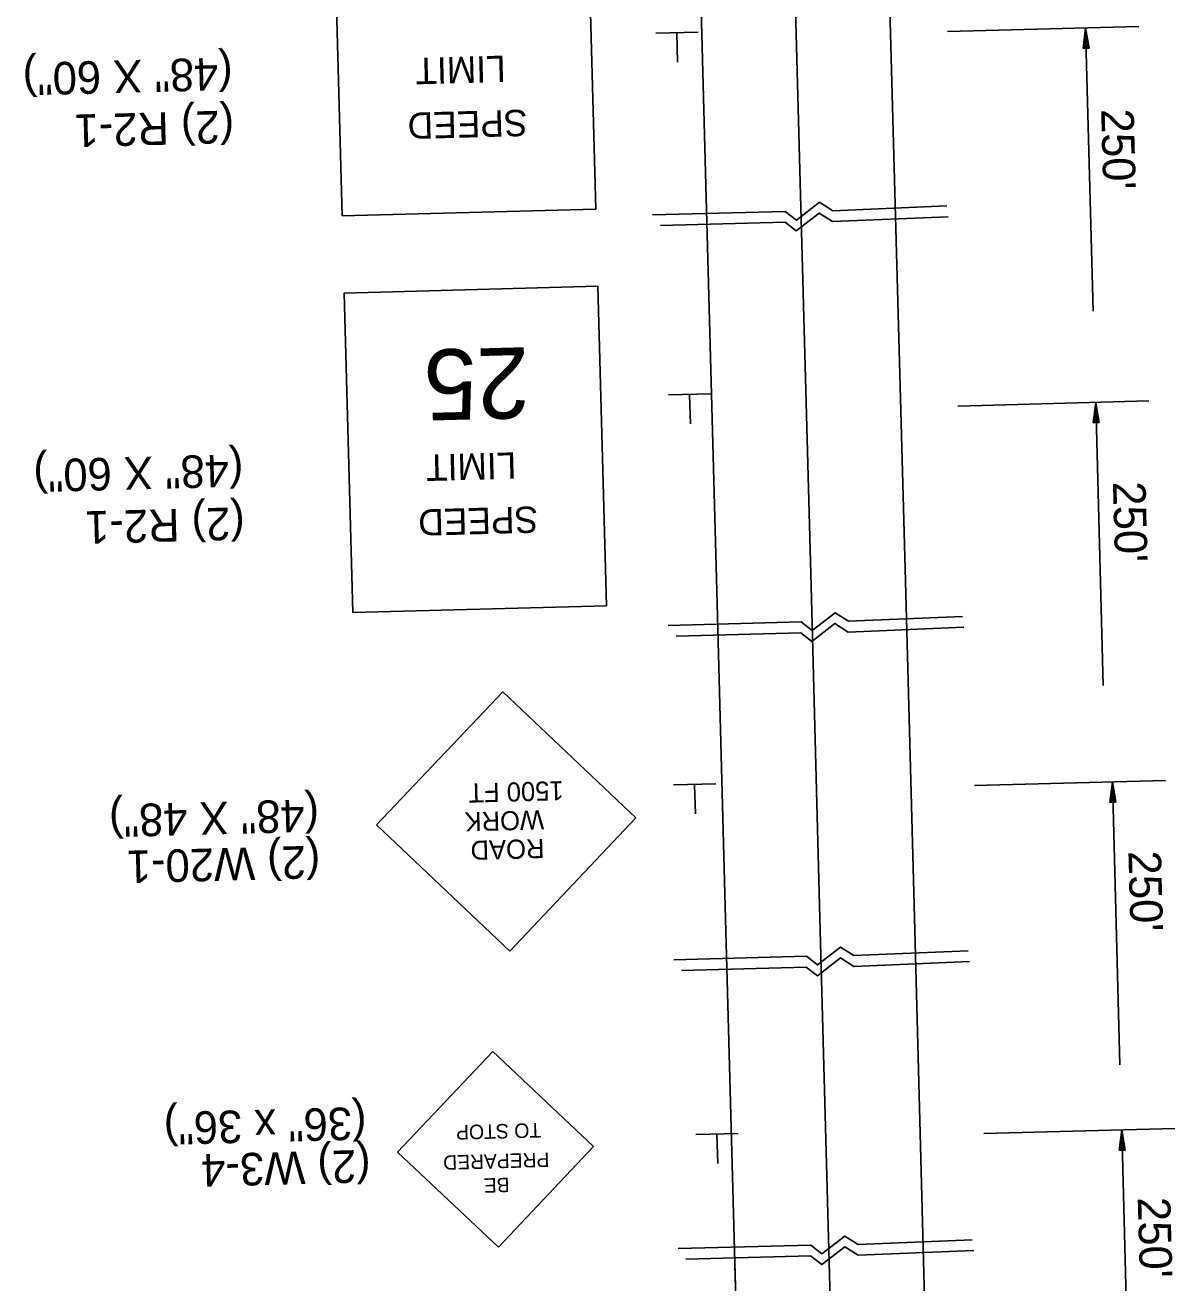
# Model space of a CAD drawing. Extents: x 1929624 to 1932072, y 596315 to 605533.
# Drawn here: x 1931202.8 to 1931414.6, y 596981 to 597212.7 of the extents above; entities that cross this region are included whole.
import ezdxf

# ---------------------------------------------------------------- set-up
doc = ezdxf.new("R2010")
doc.units = 0
doc.layers.add('Default', color=7, linetype='Continuous')

msp = doc.modelspace()

# ---------------------------------------------------------------- linework, layer by layer
at = {"layer": 'Default'}
for p, q in [((1931326.37, 597252.24), (1931328.22, 597183.26)), ((1931343.74, 597252.71), (1931345.6, 597183.73)), ((1931361.12, 597253.18), (1931362.97, 597184.2)), ((1931318.98, 597211.23), (1931326.8, 597211.44)), ((1931322.87, 597211.22), (1931323.01, 597205.88)), ((1931407.94, 597212.46), (1931372.74, 597211.52)), ((1931397.69, 597208.44), (1931398.15, 597212.2)), ((1931397.79, 597208.44), (1931398.17, 597211.57)), ((1931397.88, 597208.44), (1931398.19, 597210.93)), ((1931397.98, 597208.44), (1931398.21, 597210.31)), ((1931398.15, 597212.2), (1931399.55, 597160.03)), ((1931398.82, 597208.47), (1931398.15, 597212.2)), ((1931398.72, 597208.46), (1931398.17, 597211.57)), ((1931398.63, 597208.46), (1931398.19, 597210.93)), ((1931398.53, 597208.46), (1931398.21, 597210.31)), ((1931397.69, 597208.44), (1931398.82, 597208.47)), ((1931398.07, 597208.45), (1931398.22, 597209.67)), ((1931398.17, 597208.45), (1931398.24, 597209.04)), ((1931398.44, 597208.46), (1931398.22, 597209.67)), ((1931398.34, 597208.45), (1931398.24, 597209.04)), ((1931328.22, 597183.26), (1931330.23, 597108.43)), ((1931345.6, 597183.73), (1931347.59, 597109.36)), ((1931362.97, 597184.2), (1931364.96, 597110.29)), ((1931321.33, 597144.6), (1931329.15, 597144.81)), ((1931325.22, 597144.59), (1931325.37, 597139.25)), ((1931409.79, 597143.48), (1931374.6, 597142.54)), ((1931399.54, 597139.46), (1931400.01, 597143.22)), ((1931400.01, 597143.22), (1931401.41, 597091.05)), ((1931400.67, 597139.49), (1931400.01, 597143.22)), ((1931399.64, 597139.46), (1931400.02, 597142.6)), ((1931399.73, 597139.46), (1931400.04, 597141.95)), ((1931399.83, 597139.46), (1931400.06, 597141.33)), ((1931400.58, 597139.48), (1931400.02, 597142.6)), ((1931400.48, 597139.48), (1931400.04, 597141.95)), ((1931400.39, 597139.48), (1931400.06, 597141.33)), ((1931399.54, 597139.46), (1931400.67, 597139.49)), ((1931399.92, 597139.47), (1931400.07, 597140.69)), ((1931400.02, 597139.47), (1931400.09, 597140.06)), ((1931400.29, 597139.48), (1931400.07, 597140.69)), ((1931400.19, 597139.47), (1931400.09, 597140.06)), ((1931330.23, 597108.43), (1931331.85, 597048.08)), ((1931347.59, 597109.36), (1931349.23, 597048.2)), ((1931364.96, 597110.29), (1931366.62, 597048.33)), ((1931267.55, 597065.36), (1931290.8, 597089.88)), ((1931290.8, 597089.88), (1931315.34, 597066.65)), ((1931412.87, 597073.58), (1931377.67, 597072.63)), ((1931322.25, 597072.73), (1931330.07, 597072.94)), ((1931326.14, 597072.72), (1931326.29, 597067.38)), ((1931402.62, 597069.55), (1931403.08, 597073.31)), ((1931402.71, 597069.55), (1931403.1, 597072.69)), ((1931402.81, 597069.55), (1931403.12, 597072.04)), ((1931402.9, 597069.56), (1931403.13, 597071.42)), ((1931403.08, 597073.31), (1931404.48, 597021.14)), ((1931403.75, 597069.58), (1931403.08, 597073.31)), ((1931403.65, 597069.58), (1931403.1, 597072.69)), ((1931403.56, 597069.57), (1931403.12, 597072.04)), ((1931403.46, 597069.57), (1931403.13, 597071.42)), ((1931402.62, 597069.55), (1931403.75, 597069.58)), ((1931403, 597069.56), (1931403.15, 597070.78)), ((1931403.09, 597069.56), (1931403.17, 597070.16)), ((1931403.37, 597069.57), (1931403.15, 597070.78)), ((1931403.27, 597069.57), (1931403.17, 597070.16)), ((1931292.08, 597042.11), (1931315.34, 597066.65)), ((1931267.55, 597065.36), (1931292.08, 597042.11)), ((1931331.85, 597048.08), (1931333.84, 596973.76)), ((1931349.23, 597048.2), (1931350.88, 596987.04)), ((1931366.62, 597048.33), (1931368.25, 596987.51)), ((1931271.44, 597005.06), (1931288.96, 597023.61)), ((1931288.96, 597023.61), (1931307.51, 597006.09)), ((1931414.59, 597009.44), (1931379.39, 597008.49)), ((1931404.34, 597005.41), (1931404.8, 597009.18)), ((1931404.8, 597009.18), (1931406.2, 596957.01)), ((1931405.47, 597005.44), (1931404.8, 597009.18)), ((1931326.36, 597008.33), (1931334.18, 597008.54)), ((1931330.26, 597008.32), (1931330.4, 597002.98)), ((1931404.44, 597005.41), (1931404.82, 597008.55)), ((1931404.53, 597005.42), (1931404.84, 597007.9)), ((1931404.63, 597005.42), (1931404.85, 597007.28)), ((1931404.72, 597005.42), (1931404.87, 597006.64)), ((1931405.37, 597005.44), (1931404.82, 597008.55)), ((1931405.28, 597005.44), (1931404.84, 597007.9)), ((1931405.18, 597005.43), (1931404.85, 597007.28)), ((1931405.09, 597005.43), (1931404.87, 597006.64)), ((1931271.44, 597005.06), (1931289.99, 596987.55)), ((1931289.99, 596987.55), (1931307.51, 597006.09)), ((1931404.34, 597005.41), (1931405.47, 597005.44)), ((1931404.82, 597005.42), (1931404.89, 597006.02)), ((1931404.99, 597005.43), (1931404.89, 597006.02)), ((1931333.5, 596986.58), (1931336.07, 596890.83)), ((1931350.88, 596987.04), (1931353.2, 596900.47)), ((1931368.25, 596987.51), (1931370.58, 596900.94))]:
    msp.add_line(p, q, dxfattribs=at)
for points in [[(1931261.23, 597177.58), (1931259.65, 597236.43), (1931306.34, 597237.68), (1931307.92, 597178.83)], [(1931263.19, 597104.49), (1931261.61, 597163.34), (1931308.3, 597164.6), (1931309.88, 597105.75)]]:
    msp.add_lwpolyline(points, close=True, dxfattribs=at)
for points in [[(1931372.6, 597179.41), (1931351.58, 597178.52), (1931349.13, 597180.08), (1931344.89, 597176.8), (1931342.84, 597178.41), (1931318.39, 597177.76)], [(1931372.85, 597177.42), (1931351.56, 597176.52), (1931349.1, 597178.08), (1931344.86, 597174.8), (1931342.81, 597176.41), (1931319.85, 597175.8)], [(1931375.5, 597103.78), (1931354.48, 597102.89), (1931352.02, 597104.45), (1931347.78, 597101.17), (1931345.74, 597102.78), (1931321.29, 597102.13)], [(1931375.74, 597101.79), (1931354.45, 597100.89), (1931351.99, 597102.45), (1931347.75, 597099.17), (1931345.71, 597100.78), (1931322.75, 597100.17)], [(1931376.5, 597042.17), (1931355.48, 597041.29), (1931353.02, 597042.85), (1931348.78, 597039.57), (1931346.74, 597041.18), (1931322.29, 597040.53)], [(1931376.74, 597040.18), (1931355.45, 597039.29), (1931352.99, 597040.85), (1931348.75, 597037.57), (1931346.71, 597039.18), (1931323.75, 597038.57)], [(1931377.29, 596988.95), (1931356.28, 596988.07), (1931353.82, 596989.62), (1931349.58, 596986.35), (1931347.53, 596987.96), (1931323.08, 596987.31)], [(1931377.54, 596986.96), (1931356.25, 596986.07), (1931353.79, 596987.63), (1931349.55, 596984.35), (1931347.5, 596985.96), (1931324.54, 596985.34)]]:
    msp.add_lwpolyline(points, dxfattribs=at)

# ---------------------------------------------------------------- texts
for s, height, rotation, p in [('(48" X 60")', 6, 181.5377, (1931240.99, 597206.79)), ('LIMIT', 4.865, 181.5377, (1931291.27, 597207.12)), ('(2) R2-1', 6, 181.5377, (1931241.26, 597197.02)), ('SPEED', 4.865, 181.5377, (1931295.27, 597197.17)), ("250'", 6, 271.5377, (1931401.01, 597197.23)), ('25', 13.039, 181.5377, (1931295.54, 597153.4)), ('(48" X 60")', 6, 181.5377, (1931242.96, 597133.7)), ('LIMIT', 4.865, 181.5377, (1931293.23, 597134.03)), ("250'", 6, 271.5377, (1931403.18, 597128.57)), ('(2) R2-1', 6, 181.5377, (1931243.22, 597123.93)), ('SPEED', 4.865, 181.5377, (1931297.23, 597124.08)), ('(48" X 48")', 6, 181.5377, (1931256.9, 597070.13)), ('1500 FT', 3.522, 181.5383, (1931301.96, 597073.45)), ('WORK', 3.52, 181.5377, (1931298.36, 597068.07)), ('(2) W20-1', 6, 181.5377, (1931257.13, 597061.57)), ('ROAD', 3.521, 181.5381, (1931298.43, 597062.79)), ("250'", 6, 271.5377, (1931406.03, 597060.54)), ('(36" x 36")', 6, 181.5377, (1931265.64, 597013.41)), ('TO STOP', 2.675, 181.5383, (1931297.85, 597010.46)), ('(2) W3-4', 6, 181.5377, (1931266.39, 597005.53)), ('PREPARED', 2.658, 181.638, (1931299.34, 597005.02)), ('BE', 2.658, 181.6381, (1931292.01, 597000.38)), ("250'", 6, 271.5377, (1931407.75, 596996.72))]:
    msp.add_text(s, height=height, rotation=rotation, dxfattribs=at).set_placement(p)

doc.saveas('drawing.dxf')
